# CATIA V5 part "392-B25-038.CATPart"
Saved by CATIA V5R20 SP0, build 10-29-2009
Part number: 392-B25-038
Definition: NONE
Nomenclature: 392-B25-038
Source: Unknown
Description: 392-B25-038
Bounding box of the stored display mesh (mm): x 0 to 38, y -12.35 to 12.35, z -12.25 to 12.064
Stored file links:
  C:\Users\Utente\Desktop\IO LAVORO\3D X SITO CF\X SITO\3D files 392B\392-B25-038.CATPart
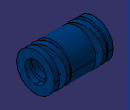
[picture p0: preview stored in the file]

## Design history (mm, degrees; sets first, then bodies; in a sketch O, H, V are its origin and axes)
Body1 "392-B25-038" (main body)
  Solid1: solid without history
